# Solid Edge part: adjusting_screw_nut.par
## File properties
Title: Adjusting screw nut
Author: Abhinav Rai
Template: Normal.par
Last saved by: CADCIM
Revision: 8
Application: Solid Edge
Material: aluminum
Accuracy: 0.99
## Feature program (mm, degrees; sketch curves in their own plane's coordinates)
sketch for "unnamed RevolvedProtrusion 1" plane through (0, 0, 0) normal (0, -1, 0) x-axis (1, 0, 0)
  line (38.1, 9.7462) -> (74.676, 9.7462)
  line (76.2, 8.2222) -> (74.676, 9.7462)
  line (76.2, -26.8298) -> (76.2, 8.2222)
  line (76.2, -26.8298) -> (74.676, -28.3538)
  line (74.676, -28.3538) -> (47.625, -28.3538)
  line (47.625, -28.3538) -> (47.625, -60.1038)
  line (47.625, -60.1038) -> (38.1, -60.1038)
  line (38.1, -60.1038) -> (38.1, 9.7462)
revolve "unnamed RevolvedProtrusion 1" add full turn 360 deg
sketch for "Hole_1" plane through (76.2, 0, 0) normal (1, 0, 0) x-axis (0, 1, 0)
  hole centre (0, -9.3038) bore radius 9.5123
hole "Hole_1" diameter 19.0246 finite  VBottomAngle = 118 deg
pattern "unnamed Pattern 1" of "Hole_1"
pattern "unnamed Pattern 2"
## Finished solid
Body 1: solid body, 16 faces, 16 edges, 4 vertices.
  Faces by surface: cylinder 7, cone 6, plane 3
  Edges by curve: circle 12, intersection 4
Bounding box of the edges (mm): 152.400 x 152.400 x 69.850, from (-76.2, -76.2, -60.1038) to (76.2, 76.2, 9.7462).
Cylindrical faces by radius (mm): R9.5123 x4, R38.1 x1, R47.625 x1, R76.2 x1
Conical faces (half-angle, radius in mm at the cone's reference point): 45 deg R74.676 x1, 45 deg R76.2 x1, 59 deg R9.5123 x4
Planar faces by outward normal: +z 1, -z 2
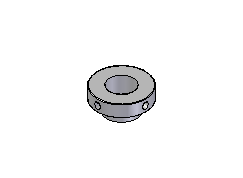
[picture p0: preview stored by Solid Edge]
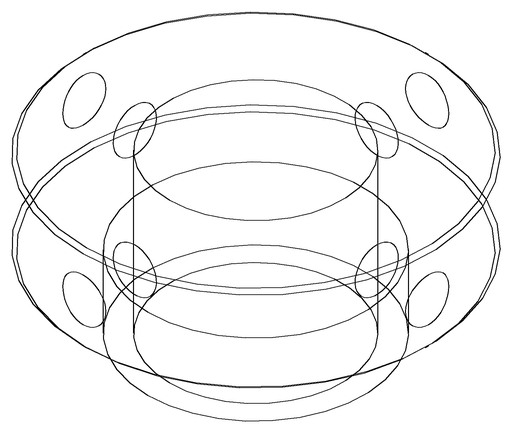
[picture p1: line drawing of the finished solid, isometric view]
